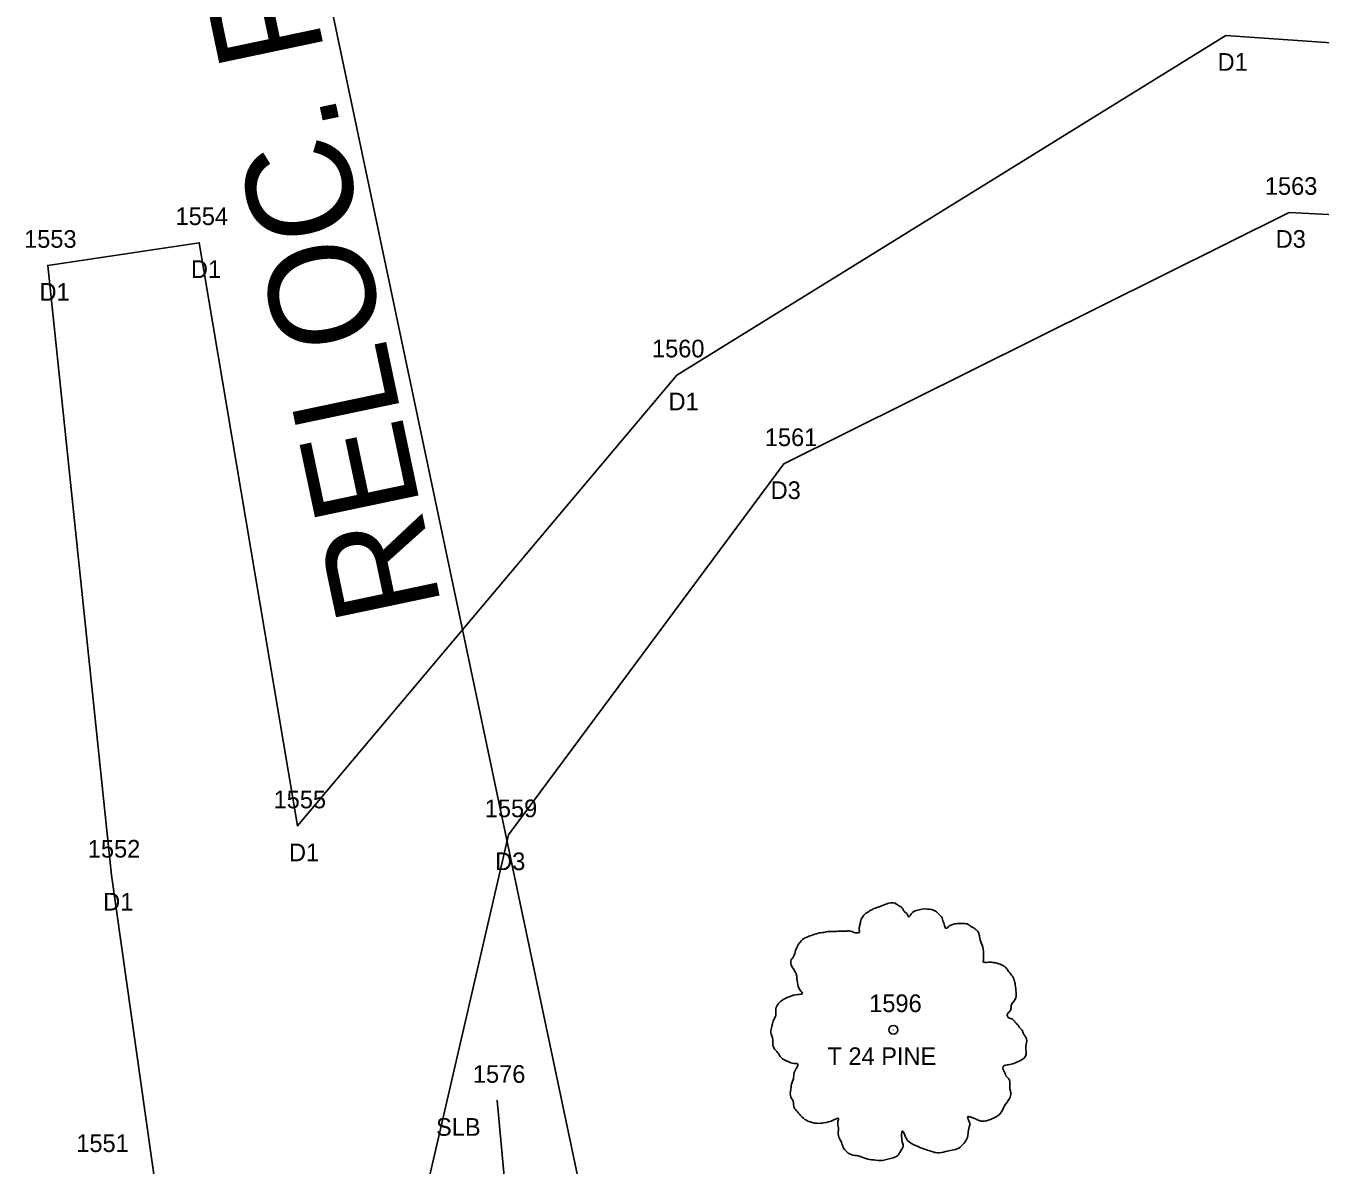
# Model space of a CAD drawing. Extents: x 1964982 to 1970452, y 1116335 to 1119906.
# Drawn here: x 1966566.7 to 1966640.1, y 1117464.3 to 1117528.9 of the extents above; entities that cross this region are included whole.
import ezdxf

# ---------------------------------------------------------------- set-up
doc = ezdxf.new("R2010")
doc.units = 0
for name, color, linetype in [('RD_EX_Driveway', 7, 'Continuous'), ('RD_EX_Driveway_txCode', 7, 'Continuous'), ('RD_EX_VEG', 7, 'Continuous'), ('RD_EX_VEG_txCode', 7, 'Continuous'), ('RD_HC_CL_Rel', 7, 'Continuous'), ('RD_HC_Data_Rel', 7, 'Continuous'), ('RD_PD_Final_TrvlWay', 7, 'Continuous'), ('RD_SMD_Locator', 7, 'Continuous')]:
    doc.layers.add(name, color=color, linetype=linetype)

msp = doc.modelspace()

# ---------------------------------------------------------------- linework, layer by layer
at = {"layer": 'RD_EX_Driveway'}
for points in [[(1966578.028, 1117435.239), (1966571.581, 1117480.753), (1966567.97, 1117515.311), (1966576.556, 1117516.6), (1966582.112, 1117483.547), (1966603.624, 1117509.102), (1966634.749, 1117528.345), (1966662.085, 1117526.43), (1966689.524, 1117514.663), (1966711.523, 1117497.722), (1966730.008, 1117478.512), (1966744.031, 1117462.693), (1966734.107, 1117458.19)], [(1966589.3, 1117436.331), (1966587.977, 1117456.65), (1966594.083, 1117483.042), (1966609.697, 1117504.074), (1966638.325, 1117518.314), (1966661.317, 1117517.134), (1966685.434, 1117507.038), (1966705.558, 1117491.043), (1966722.871, 1117472.119), (1966734.107, 1117458.19)]]:
    msp.add_lwpolyline(points, dxfattribs=at)
at = {"layer": 'RD_EX_VEG'}
msp.add_line((1966597.045, 1117429.245), (1966593.432, 1117467.989), dxfattribs=at)
for centre, radius in [((1966615.898, 1117471.997), 0.25), ((1966615.898, 1117471.997), 0.25), ((1966615.886, 1117471.978), 0.0001), ((1966615.886, 1117471.978), 0.0001)]:
    msp.add_circle(centre, radius, dxfattribs=at)
for points in [[(1966616.03, 1117479.164), (1966615.73, 1117479.189), (1966615.405, 1117479.089), (1966615.156, 1117478.989), (1966614.931, 1117478.914), (1966614.706, 1117478.814), (1966614.406, 1117478.639), (1966614.181, 1117478.439), (1966614.056, 1117478.189), (1966614.006, 1117477.965), (1966613.956, 1117477.69), (1966613.956, 1117477.515), (1966613.831, 1117477.49), (1966613.681, 1117477.515), (1966613.431, 1117477.59), (1966613.181, 1117477.59), (1966612.931, 1117477.59), (1966612.582, 1117477.565), (1966612.232, 1117477.565), (1966611.957, 1117477.515), (1966611.632, 1117477.465), (1966611.257, 1117477.34), (1966610.907, 1117477.215), (1966610.608, 1117476.965), (1966610.358, 1117476.49), (1966610.233, 1117476.14), (1966610.083, 1117475.89), (1966610.233, 1117475.441), (1966610.408, 1117475.091), (1966610.433, 1117474.891), (1966610.508, 1117474.466), (1966610.608, 1117474.241), (1966610.732, 1117474.041), (1966610.658, 1117474.016), (1966610.283, 1117473.966), (1966609.983, 1117473.866), (1966609.558, 1117473.641), (1966609.333, 1117473.417), (1966609.233, 1117473.092), (1966609.208, 1117472.742), (1966609.108, 1117472.542), (1966609.033, 1117472.267), (1966609.008, 1117472.192), (1966608.958, 1117471.867), (1966609.058, 1117471.417), (1966609.083, 1117471.068), (1966609.208, 1117470.843), (1966609.358, 1117470.668), (1966609.533, 1117470.418), (1966609.933, 1117470.193), (1966610.258, 1117470.093), (1966610.458, 1117470.068), (1966610.283, 1117469.568), (1966610.233, 1117469.218), (1966610.108, 1117468.819), (1966610.108, 1117468.744), (1966610.058, 1117468.269), (1966610.208, 1117467.944), (1966610.283, 1117467.569), (1966610.458, 1117467.344), (1966610.732, 1117467.044), (1966611.057, 1117466.819), (1966611.557, 1117466.694), (1966611.957, 1117466.719), (1966612.532, 1117466.894), (1966612.782, 1117466.969), (1966612.757, 1117466.794), (1966612.782, 1117466.42), (1966612.782, 1117465.995), (1966612.931, 1117465.67), (1966613.031, 1117465.395), (1966613.181, 1117465.145), (1966613.506, 1117464.92), (1966613.906, 1117464.845), (1966614.331, 1117464.695), (1966614.781, 1117464.62), (1966615.28, 1117464.595), (1966615.88, 1117464.745), (1966616.155, 1117464.87), (1966616.255, 1117465.045), (1966616.455, 1117465.42), (1966616.405, 1117465.645), (1966616.43, 1117466.245), (1966616.53, 1117466.07), (1966616.705, 1117465.72), (1966617.205, 1117465.42), (1966617.604, 1117465.245), (1966618.079, 1117465.095), (1966618.379, 1117465.02), (1966618.854, 1117465.095), (1966619.229, 1117465.17), (1966619.604, 1117465.295), (1966619.903, 1117465.57), (1966620.078, 1117465.845), (1966620.128, 1117466.12), (1966620.203, 1117466.495), (1966620.253, 1117466.669)], [(1966616.03, 1117479.164), (1966615.73, 1117479.189), (1966615.405, 1117479.089), (1966615.156, 1117478.989), (1966614.931, 1117478.914), (1966614.706, 1117478.814), (1966614.406, 1117478.639), (1966614.181, 1117478.439), (1966614.056, 1117478.189), (1966614.006, 1117477.965), (1966613.956, 1117477.69), (1966613.956, 1117477.515), (1966613.831, 1117477.49), (1966613.681, 1117477.515), (1966613.431, 1117477.59), (1966613.181, 1117477.59), (1966612.931, 1117477.59), (1966612.582, 1117477.565), (1966612.232, 1117477.565), (1966611.957, 1117477.515), (1966611.632, 1117477.465), (1966611.257, 1117477.34), (1966610.907, 1117477.215), (1966610.608, 1117476.965), (1966610.358, 1117476.49), (1966610.233, 1117476.14), (1966610.083, 1117475.89), (1966610.233, 1117475.441), (1966610.408, 1117475.091), (1966610.433, 1117474.891), (1966610.508, 1117474.466), (1966610.608, 1117474.241), (1966610.732, 1117474.041), (1966610.658, 1117474.016), (1966610.283, 1117473.966), (1966609.983, 1117473.866), (1966609.558, 1117473.641), (1966609.333, 1117473.417), (1966609.233, 1117473.092), (1966609.208, 1117472.742), (1966609.108, 1117472.542), (1966609.033, 1117472.267), (1966609.008, 1117472.192), (1966608.958, 1117471.867), (1966609.058, 1117471.417), (1966609.083, 1117471.068), (1966609.208, 1117470.843), (1966609.358, 1117470.668), (1966609.533, 1117470.418), (1966609.933, 1117470.193), (1966610.258, 1117470.093), (1966610.458, 1117470.068), (1966610.283, 1117469.568), (1966610.233, 1117469.218), (1966610.108, 1117468.819), (1966610.108, 1117468.744), (1966610.058, 1117468.269), (1966610.208, 1117467.944), (1966610.283, 1117467.569), (1966610.458, 1117467.344), (1966610.732, 1117467.044), (1966611.057, 1117466.819), (1966611.557, 1117466.694), (1966611.957, 1117466.719), (1966612.532, 1117466.894), (1966612.782, 1117466.969), (1966612.757, 1117466.794), (1966612.782, 1117466.42), (1966612.782, 1117465.995), (1966612.931, 1117465.67), (1966613.031, 1117465.395), (1966613.181, 1117465.145), (1966613.506, 1117464.92), (1966613.906, 1117464.845), (1966614.331, 1117464.695), (1966614.781, 1117464.62), (1966615.28, 1117464.595), (1966615.88, 1117464.745), (1966616.155, 1117464.87), (1966616.255, 1117465.045), (1966616.455, 1117465.42), (1966616.405, 1117465.645), (1966616.43, 1117466.245), (1966616.53, 1117466.07), (1966616.705, 1117465.72), (1966617.205, 1117465.42), (1966617.604, 1117465.245), (1966618.079, 1117465.095), (1966618.379, 1117465.02), (1966618.854, 1117465.095), (1966619.229, 1117465.17), (1966619.604, 1117465.295), (1966619.903, 1117465.57), (1966620.078, 1117465.845), (1966620.128, 1117466.12), (1966620.203, 1117466.495), (1966620.253, 1117466.669)], [(1966620.253, 1117466.669), (1966620.178, 1117466.844), (1966620.128, 1117467.094), (1966620.203, 1117467.069), (1966620.378, 1117467.019), (1966620.653, 1117466.894), (1966620.878, 1117466.819), (1966621.203, 1117466.844), (1966621.478, 1117466.944), (1966621.928, 1117467.219), (1966622.202, 1117467.694), (1966622.477, 1117468.094), (1966622.552, 1117468.419), (1966622.502, 1117468.644), (1966622.477, 1117469.143), (1966622.277, 1117469.393), (1966622.227, 1117469.518), (1966622.127, 1117469.918), (1966622.202, 1117469.968), (1966622.477, 1117470.018), (1966622.852, 1117470.143), (1966623.127, 1117470.268), (1966623.352, 1117470.443), (1966623.427, 1117470.668), (1966623.402, 1117471.068), (1966623.452, 1117471.467), (1966623.377, 1117471.617), (1966623.277, 1117471.767), (1966623.202, 1117471.967), (1966623.052, 1117472.117), (1966622.952, 1117472.267), (1966622.852, 1117472.367), (1966622.727, 1117472.517), (1966622.552, 1117472.642), (1966622.402, 1117472.692), (1966622.352, 1117472.842), (1966622.502, 1117473.042), (1966622.552, 1117473.142), (1966622.577, 1117473.367), (1966622.802, 1117473.716), (1966622.852, 1117474.116), (1966622.802, 1117474.541), (1966622.752, 1117474.816), (1966622.602, 1117475.091), (1966622.402, 1117475.341), (1966622.277, 1117475.516), (1966622.102, 1117475.641), (1966621.778, 1117475.766), (1966621.528, 1117475.815), (1966621.178, 1117475.815), (1966620.978, 1117475.865), (1966621.003, 1117475.915), (1966621.003, 1117476.065), (1966621.003, 1117476.34), (1966620.928, 1117476.79), (1966620.778, 1117477.29), (1966620.778, 1117477.315), (1966620.678, 1117477.565), (1966620.453, 1117477.765), (1966620.278, 1117477.865), (1966620.078, 1117477.99), (1966619.828, 1117478.015), (1966619.529, 1117478.015), (1966619.254, 1117477.965), (1966619.054, 1117477.865), (1966618.879, 1117477.74), (1966618.804, 1117477.89), (1966618.704, 1117478.189), (1966618.654, 1117478.339), (1966618.504, 1117478.514), (1966618.279, 1117478.714), (1966617.829, 1117478.839), (1966617.205, 1117478.764), (1966616.905, 1117478.564), (1966616.755, 1117478.389), (1966616.705, 1117478.514), (1966616.505, 1117478.714), (1966616.405, 1117478.889), (1966616.23, 1117479.014), (1966616.08, 1117479.114), (1966615.98, 1117479.164)], [(1966620.253, 1117466.669), (1966620.178, 1117466.844), (1966620.128, 1117467.094), (1966620.203, 1117467.069), (1966620.378, 1117467.019), (1966620.653, 1117466.894), (1966620.878, 1117466.819), (1966621.203, 1117466.844), (1966621.478, 1117466.944), (1966621.928, 1117467.219), (1966622.202, 1117467.694), (1966622.477, 1117468.094), (1966622.552, 1117468.419), (1966622.502, 1117468.644), (1966622.477, 1117469.143), (1966622.277, 1117469.393), (1966622.227, 1117469.518), (1966622.127, 1117469.918), (1966622.202, 1117469.968), (1966622.477, 1117470.018), (1966622.852, 1117470.143), (1966623.127, 1117470.268), (1966623.352, 1117470.443), (1966623.427, 1117470.668), (1966623.402, 1117471.068), (1966623.452, 1117471.467), (1966623.377, 1117471.617), (1966623.277, 1117471.767), (1966623.202, 1117471.967), (1966623.052, 1117472.117), (1966622.952, 1117472.267), (1966622.852, 1117472.367), (1966622.727, 1117472.517), (1966622.552, 1117472.642), (1966622.402, 1117472.692), (1966622.352, 1117472.842), (1966622.502, 1117473.042), (1966622.552, 1117473.142), (1966622.577, 1117473.367), (1966622.802, 1117473.716), (1966622.852, 1117474.116), (1966622.802, 1117474.541), (1966622.752, 1117474.816), (1966622.602, 1117475.091), (1966622.402, 1117475.341), (1966622.277, 1117475.516), (1966622.102, 1117475.641), (1966621.778, 1117475.766), (1966621.528, 1117475.815), (1966621.178, 1117475.815), (1966620.978, 1117475.865), (1966621.003, 1117475.915), (1966621.003, 1117476.065), (1966621.003, 1117476.34), (1966620.928, 1117476.79), (1966620.778, 1117477.29), (1966620.778, 1117477.315), (1966620.678, 1117477.565), (1966620.453, 1117477.765), (1966620.278, 1117477.865), (1966620.078, 1117477.99), (1966619.828, 1117478.015), (1966619.529, 1117478.015), (1966619.254, 1117477.965), (1966619.054, 1117477.865), (1966618.879, 1117477.74), (1966618.804, 1117477.89), (1966618.704, 1117478.189), (1966618.654, 1117478.339), (1966618.504, 1117478.514), (1966618.279, 1117478.714), (1966617.829, 1117478.839), (1966617.205, 1117478.764), (1966616.905, 1117478.564), (1966616.755, 1117478.389), (1966616.705, 1117478.514), (1966616.505, 1117478.714), (1966616.405, 1117478.889), (1966616.23, 1117479.014), (1966616.08, 1117479.114), (1966615.98, 1117479.164)]]:
    msp.add_spline(points, degree=3, dxfattribs=at)
at = {"layer": 'RD_HC_CL_Rel'}
msp.add_arc((1966373.74, 1118527.456), 1145.915, 281.904723, 295.046328, dxfattribs=at)
at = {"layer": 'RD_HC_Data_Rel'}
msp.add_line((1966610.125, 1117406.187), (1966579.812, 1117549.972), dxfattribs=at)
at = {"layer": 'RD_PD_Final_TrvlWay'}
for radius in [1134.915, 1156.915]:
    msp.add_arc((1966373.74, 1118527.456), radius, 281.904723, 295.046328, dxfattribs=at)
at = {"layer": 'RD_SMD_Locator'}
for centre in [(1966634.749, 1117528.345), (1966634.749, 1117528.345), (1966638.325, 1117518.314), (1966638.325, 1117518.314), (1966576.556, 1117516.6), (1966576.556, 1117516.6), (1966567.97, 1117515.311), (1966567.97, 1117515.311), (1966603.624, 1117509.102), (1966603.624, 1117509.102), (1966609.697, 1117504.074), (1966609.697, 1117504.074), (1966582.112, 1117483.547), (1966582.112, 1117483.547), (1966594.083, 1117483.042), (1966594.083, 1117483.042), (1966571.581, 1117480.753), (1966571.581, 1117480.753), (1966593.432, 1117467.989), (1966593.432, 1117467.989)]:
    msp.add_circle(centre, 0.001, dxfattribs=at)

# ---------------------------------------------------------------- texts
at = {"layer": 'RD_EX_Driveway_txCode'}
for s, p in [('D1', (1966634.276, 1117526.345)), ('D1', (1966634.276, 1117526.345)), ('1563', (1966636.955, 1117519.314)), ('1563', (1966636.955, 1117519.314)), ('1554', (1966575.209, 1117517.6)), ('1554', (1966575.209, 1117517.6)), ('1553', (1966566.623, 1117516.311)), ('1553', (1966566.623, 1117516.311)), ('D3', (1966637.569, 1117516.314)), ('D3', (1966637.569, 1117516.314)), ('D1', (1966576.083, 1117514.6)), ('D1', (1966576.083, 1117514.6)), ('D1', (1966567.497, 1117513.311)), ('D1', (1966567.497, 1117513.311)), ('1560', (1966602.215, 1117510.102)), ('1560', (1966602.215, 1117510.102)), ('D1', (1966603.152, 1117507.102)), ('D1', (1966603.152, 1117507.102)), ('1561', (1966608.611, 1117505.074)), ('1561', (1966608.611, 1117505.074)), ('D3', (1966608.941, 1117502.074)), ('D3', (1966608.941, 1117502.074)), ('1555', (1966580.765, 1117484.547)), ('1555', (1966580.765, 1117484.547)), ('1559', (1966592.736, 1117484.042)), ('1559', (1966592.736, 1117484.042)), ('1552', (1966570.235, 1117481.753)), ('1552', (1966570.235, 1117481.753)), ('D1', (1966581.639, 1117481.547)), ('D1', (1966581.639, 1117481.547)), ('D3', (1966593.327, 1117481.042)), ('D3', (1966593.327, 1117481.042)), ('D1', (1966571.109, 1117478.753)), ('D1', (1966571.109, 1117478.753))]:
    msp.add_text(s, height=1, dxfattribs=at).set_placement(p)
at = {"layer": 'RD_EX_VEG_txCode'}
for s, p in [('1596', (1966614.528, 1117472.997)), ('1596', (1966614.528, 1117472.997)), ('T 24 PINE', (1966612.162, 1117469.997)), ('T 24 PINE', (1966612.162, 1117469.997)), ('1576', (1966592.062, 1117468.989)), ('1576', (1966592.062, 1117468.989)), ('SLB', (1966589.975, 1117465.989)), ('SLB', (1966589.975, 1117465.989)), ('1551', (1966569.583, 1117465.069)), ('1551', (1966569.583, 1117465.069))]:
    msp.add_text(s, height=1, dxfattribs=at).set_placement(p)
at = {"layer": 'RD_HC_Data_Rel'}
msp.add_text('RELOC. PC=48+33.73', height=6, rotation=101.90472, dxfattribs=at).set_placement((1966590.311, 1117495.963))

doc.saveas('drawing.dxf')
